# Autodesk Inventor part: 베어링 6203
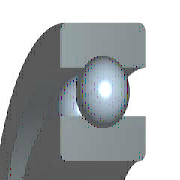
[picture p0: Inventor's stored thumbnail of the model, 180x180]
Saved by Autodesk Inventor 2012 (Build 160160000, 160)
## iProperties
IsCustomPart: 0
Company: 한국ATC센터
Created: 2014-10
Part Number: 베어링 6203
Material: Steel, Mild
Description: 깊은 그루브 볼 베어링
Document SubType Name: Modeling
Standard: KS B 2023
Designer: KYOUNG IL JANG
Standards Organization: KS
Language: ko-KR
Size Designation: 6203 - 17 x 40 x 12
Categories: <MemberInstance><Categories><Category DisplayName="샤프트 부품" InternalName="7f7aeb1f-a693-4053-b835-cee3144e0d98" Mnemonic="SHFT"><Category DisplayName="베어링" Inter
Density: 7.86 g/cm^3
Mass: 64.9809 g
Surface Area: 64.3582 cm^2
Volume: 8.26729 cm^3
Author: KYOUNG IL JANG
Revision Number: 1
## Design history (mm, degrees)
revolve "본체" stored, may be unused: angle "d6" = 90 deg
revolve "볼" stored, may be unused: angle "d7" = 90 deg
pattern_circular "IDS_ARRAYBALL[SIMPL:T]" dims angle "d3" = 360 deg
body "Solid1"
sketch "스케치" dims "d0" = 5.98 (= -0.26 x WD + 0.26 x BD)
  geometry: L1 (3.01, 14.25)-(8.99, 14.25); L2 (6, 14.25)-(6, 11.26); L3 (6, 14.25)-(6, 17.24); L4 (3.778, 12.249)-(0, 12.249); L5 (0, 8.5)-(12, 8.5); L6 (3.778, 16.251)-(0, 16.251); L7 (0, 20)-(12, 20); L8 (12, 8.5)-(12, 12.249); L9 (8.222, 12.249)-(12, 12.249); L10 (8.222, 16.251)-(12, 16.251); L11 (12, 20)-(12, 16.251); L12 (-1.4, 0)-(8.4, 0) reference; L13 (0, -0.3)-(0, 5.3) reference
  constraints: 22 end point, 4 point on line, 2 collinear, 2 perpendicular, 2 symmetric about line, 1 midpoint, 1 parallel, 14 other
  dimensions: "d9" = 17 diameter of L5 L12 (= WD); "d11" = 40 diameter of L7 L12 (= BD); "d12" = 12 distance between parallel lines of L8 L13 (= KB); "d13" = 24.498 diameter of L9 L12 (= 0.326 x BD + 0.674 x WD)
fillet "모깎기1" dims "d1" = 0.6 (= KRS)
other parameters: "WD" = 17 [user parameter; used in 5 equation terms], "BD" = 40 [user parameter; used in 5 equation terms], "KB" = 12 [user parameter; used in 1 equation term], "KRS" = 0.6 [user parameter; used in 1 equation term], "d4" = 0, "d5" = 0, "d8" = 0, "d14" = 0, "d15" = 0, "BBA" = 0 [user parameter], "BC0" = 4750000 [user parameter], "BC" = 9560000 [user parameter], "WR" = 8.5 (= 0.5 x WD) [user parameter]
